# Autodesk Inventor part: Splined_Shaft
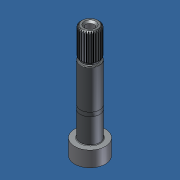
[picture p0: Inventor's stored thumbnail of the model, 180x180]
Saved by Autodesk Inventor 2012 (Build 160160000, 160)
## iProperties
Created: 2013-10
Part Number: Splined_Shaft
Material: Default
Document SubType Name: Modeling
Designer: Admin
Density: 1 g/cm^3
Author: Admin
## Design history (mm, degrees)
node "Splined_Shaft1"
node "Base1"
body "Solid1"
